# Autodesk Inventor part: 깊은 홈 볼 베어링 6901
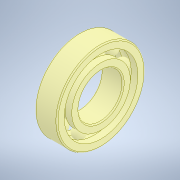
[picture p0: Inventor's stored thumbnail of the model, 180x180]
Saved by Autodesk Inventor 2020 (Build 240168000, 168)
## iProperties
Created: 2024-05
Part Number: 깊은 홈 볼 베어링 6901
Material: 강철, 연강
Description: 깊은 그루브 볼 베어링
Document SubType Name: Modeling
Designer: oem
Density: 7.85 g/cm^3
Appearance: 기본값
Author: jhkim
Sending System: Autodesk Inventor 2025
Preprocessor: ST-DEVELOPER v20
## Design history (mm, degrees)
feature "Solid1"
feature "Solid1:1"
feature "Solid1:2"
feature "Solid1:3"
feature "Solid1:4"
feature "Solid1:5"
feature "Solid1:6"
feature "Solid1:7"
feature "Solid1:8"
feature "Solid1:9"
feature "Solid1:10"
node "솔리드1"
node "솔리드2"
node "솔리드3"
node "솔리드4"
node "솔리드5"
node "솔리드6"
node "솔리드7"
node "솔리드8"
node "솔리드9"
node "솔리드10"
node "솔리드11"
